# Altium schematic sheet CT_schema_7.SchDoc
size 274 x 160 mm
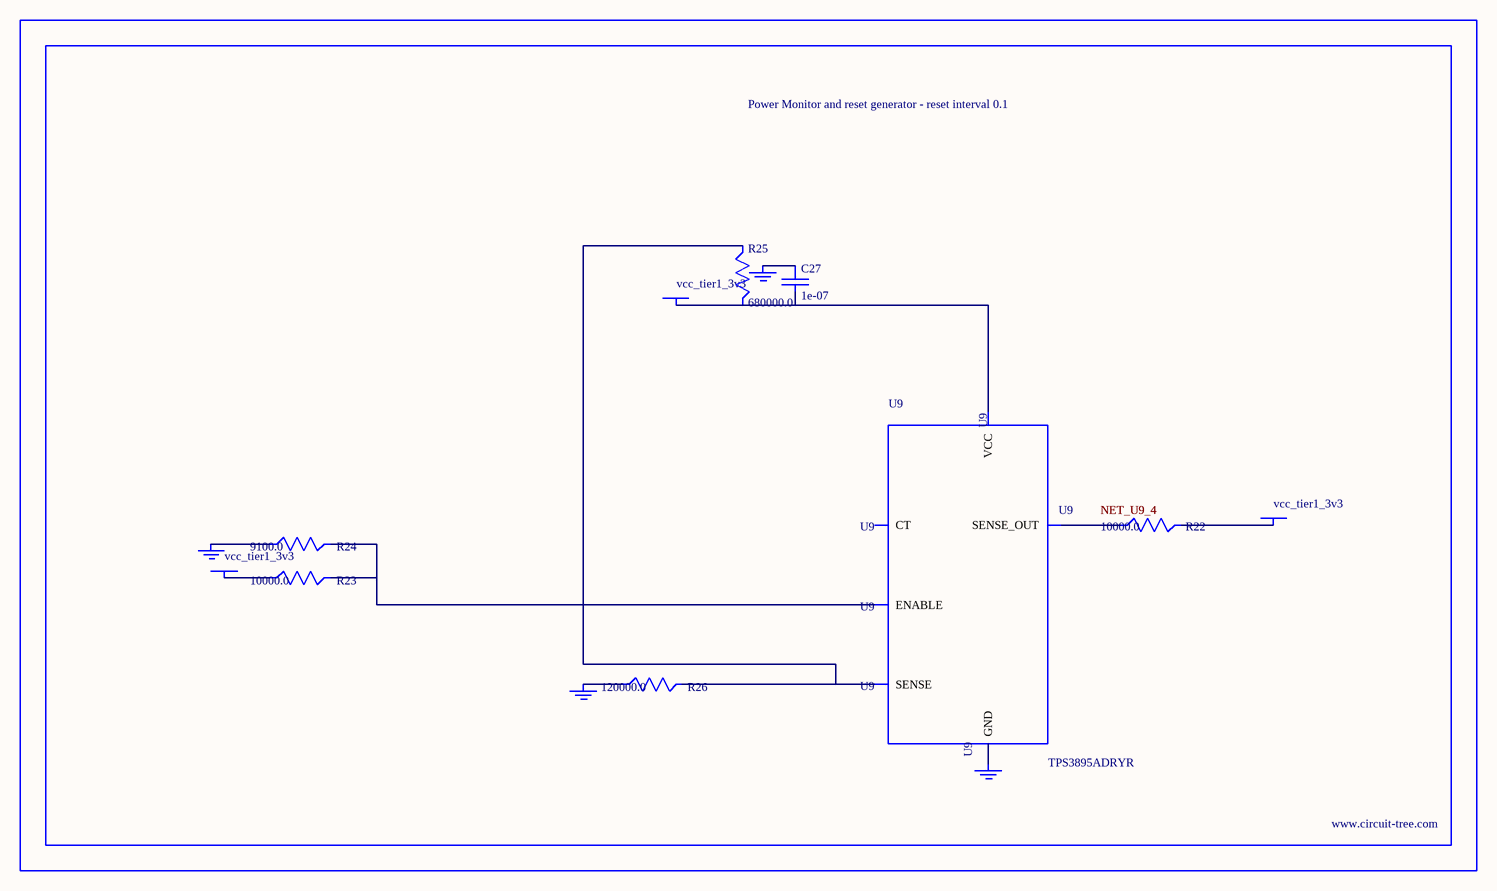
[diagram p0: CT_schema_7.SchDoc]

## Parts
BORDER6  (no value)
C27  1e-07  [C0402]
GND_INSTANCE_6_0  (no value)
GND_INSTANCE_6_1  (no value)
GND_INSTANCE_6_2  (no value)
GND_INSTANCE_6_3  (no value)
POWER_INSTANCE_6_0  vcc_tier1_3v3
POWER_INSTANCE_6_1  vcc_tier1_3v3
POWER_INSTANCE_6_2  vcc_tier1_3v3
R22  10000.0  [R0603]
R23  10000.0  [R0603]
R24  9100.0  [R0603]
R25  680000.0  [R0603]
R26  120000.0  [R0603]
U9  TPS3895ADRYR  [SON-6]

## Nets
NetC27_1: C27.1 GND_INSTANCE_6_2.0(GND)
NetC27_2: C27.2 POWER_INSTANCE_6_2.0(PWR) R25.2 U9.6(VCC)
NetGND_INSTANCE_6_0_0: GND_INSTANCE_6_0.0(GND) R24.1
NetGND_INSTANCE_6_1_0: GND_INSTANCE_6_1.0(GND) R26.1
NetGND_INSTANCE_6_3_0: GND_INSTANCE_6_3.0(GND) U9.2(GND)
NetPOWER_INSTANCE_6_0_0: POWER_INSTANCE_6_0.0(PWR) R23.1
NetPOWER_INSTANCE_6_1_0: POWER_INSTANCE_6_1.0(PWR) R22.2
NetR22_1: R22.1 U9.4(SENSE_OUT)
NetR23_2: R23.2 R24.2 U9.1(ENABLE)
NetR25_1: R25.1 R26.2 U9.3(SENSE)

Not connected (* = marked no-connect by the designer): U9 5(CT)

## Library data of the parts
BORDER6 = BORDER_PAGE6
C27 = C0402C104K3RACTU
GND_INSTANCE_6_0-GND_INSTANCE_6_3 = GND
POWER_INSTANCE_6_0-POWER_INSTANCE_6_2 = PWR
R22 R23 = RC0603JR-0710KL
R24 = RC0603JR-079K1L
R25 = RC0603JR-07680KL
R26 = RC0603JR-07120KL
